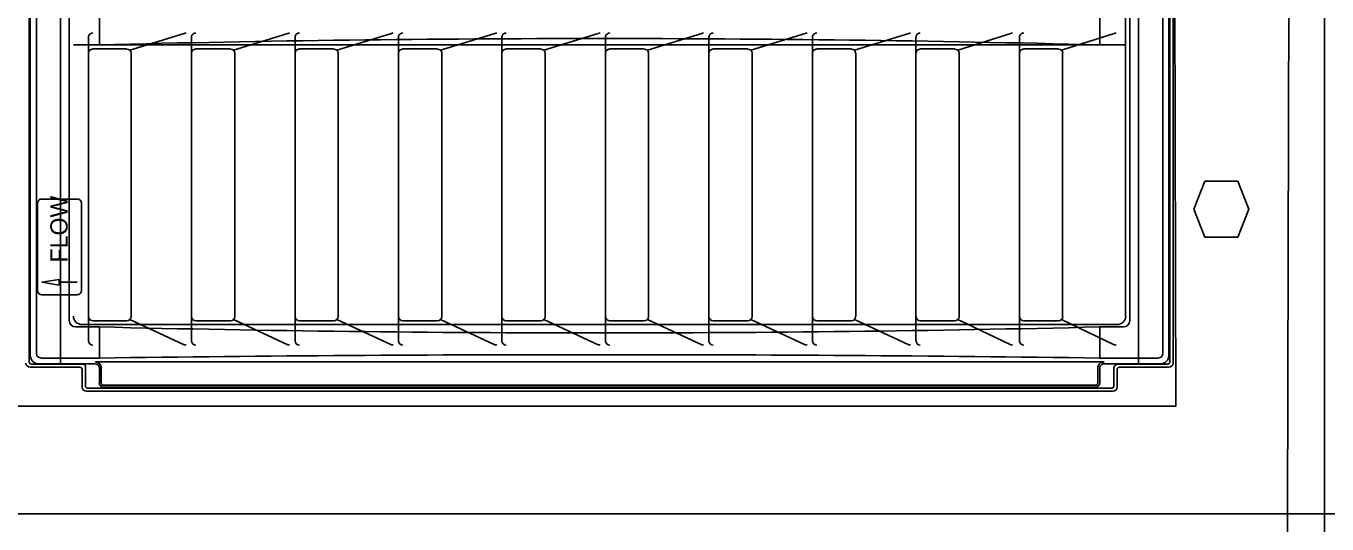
# Model space of a CAD drawing. Extents: x 9.6 to 16.8, y 2.2 to 12.2.
# Drawn here: x 12.408 to 13.549, y 10.385 to 10.822 of the extents above; entities that cross this region are included whole.
import ezdxf

# ---------------------------------------------------------------- set-up
doc = ezdxf.new("R2010")
doc.units = 0
for name, color, linetype in [('DETL-DIMS', 7, 'Continuous'), ('DETL-LINE', 7, 'Continuous'), ('DETL-NOTE', 7, 'Continuous')]:
    doc.layers.add(name, color=color, linetype=linetype)

msp = doc.modelspace()

# ---------------------------------------------------------------- linework, layer by layer
at = {"layer": 'DETL-DIMS'}
for q in [(13.5141, 10.0694), (13.9374, 10.3938)]:
    msp.add_line((13.5141, 10.3938), q, dxfattribs=at)
at = {"layer": 'DETL-LINE'}
for p, q in [((13.5464, 10.3172), (13.5464, 11.6582)), ((13.4162, 10.4884), (13.4137, 11.418)), ((13.5167, 11.4178), (13.5141, 10.3937)), ((12.4104, 10.527), (12.4104, 11.3973)), ((12.4378, 10.5253), (12.4378, 11.3968)), ((13.3835, 10.5253), (13.3835, 11.3968)), ((13.4109, 10.527), (13.4109, 11.3973)), ((13.4137, 10.5261), (13.4137, 11.3982)), ((12.4167, 10.5342), (12.4167, 11.388)), ((13.4046, 10.5342), (13.4046, 11.388)), ((12.4455, 10.5633), (12.4455, 11.3559)), ((13.3721, 10.5672), (13.3721, 11.355)), ((13.3758, 10.5633), (13.3758, 11.3589)), ((12.4719, 10.8052), (12.4719, 10.8383)), ((13.3494, 10.8052), (13.3494, 10.8383)), ((13.3721, 10.8052), (12.4492, 10.8052)), ((13.4318, 10.6611), (13.4417, 10.6858)), ((13.4417, 10.6858), (13.4704, 10.6858)), ((13.4704, 10.6858), (13.4803, 10.6611)), ((13.4417, 10.6365), (13.4318, 10.6611)), ((13.4803, 10.6611), (13.4704, 10.6365)), ((13.4704, 10.6365), (13.4417, 10.6365)), ((12.4719, 10.5578), (12.4512, 10.5578)), ((12.4567, 10.5599), (13.3646, 10.5599)), ((12.4719, 10.5305), (12.4719, 10.5578)), ((13.3494, 10.5578), (13.3701, 10.5578)), ((13.3494, 10.5305), (13.3494, 10.5578)), ((12.4548, 10.5224), (12.4113, 10.5224)), ((12.4577, 10.5252), (12.4123, 10.5252)), ((12.4719, 10.5305), (12.4205, 10.5305)), ((12.4378, 10.5252), (12.4378, 10.5253)), ((12.4596, 10.5059), (12.4596, 10.5233)), ((13.3532, 10.5271), (12.4688, 10.5271)), ((12.4736, 10.5086), (12.4736, 10.5217)), ((13.3476, 10.5086), (13.3476, 10.5217)), ((13.4008, 10.5305), (13.3494, 10.5305)), ((13.3617, 10.5059), (13.3617, 10.5215)), ((13.409, 10.5252), (13.3655, 10.5252)), ((13.41, 10.5224), (13.3665, 10.5224)), ((13.3835, 10.5252), (13.3835, 10.5253)), ((12.4567, 10.505), (12.4567, 10.5206)), ((13.3646, 10.505), (13.3646, 10.5206)), ((13.3608, 10.5013), (12.4605, 10.5013)), ((13.3598, 10.5041), (12.4615, 10.5041)), ((13.3456, 10.5067), (12.4756, 10.5067)), ((11.3604, 10.4884), (13.4162, 10.4884)), ((11.2685, 10.3938), (13.5141, 10.3938))]:
    msp.add_line(p, q, dxfattribs=at)
for centre, major_axis, start_param, end_param in [((12.9106, -5.5583), (16.9691, 0), 1.544936, 1.596657), ((12.4567, 10.5672), (0.00757, 0), 3.141593, 4.712389), ((13.3646, 10.5672), (0.00757, 0), 4.712389, 6.283185), ((12.4512, 10.5633), (0.00567, 0), 3.141593, 4.712389), ((12.9106, 27.6743), (17.7494, 0), 4.687666, 4.737112), ((13.3701, 10.5633), (0.00567, 0), 4.712389, 6.283185), ((12.4205, 10.5342), (0.00378, 0), 3.141593, 4.712389), ((12.9106, -20.1548), (31.8132, 0), 1.557003, 1.584589), ((13.4008, 10.5342), (0.00378, 0), 4.712389, 6.283185), ((12.4113, 10.5261), (0.00378, 0), 3.141593, 4.712389), ((12.4123, 10.527), (0.00189, 0), 3.141593, 4.712389), ((12.4548, 10.5206), (0.00189, 0), 0, 1.570796), ((12.4577, 10.5233), (0.00189, 0), 0, 1.570796), ((12.4681, 10.5217), (0.00556, 0), 0, 1.570796), ((13.3532, 10.5217), (0.00556, 0), 1.570796, 3.141593), ((13.3655, 10.5215), (0.00378, 0), 1.570796, 3.141593), ((13.3665, 10.5206), (0.00189, 0), 1.570796, 3.141593), ((13.409, 10.527), (0.00189, 0), 4.712389, 6.283185), ((13.41, 10.5261), (0.00378, 0), 4.712389, 6.283185), ((12.4605, 10.505), (0.00378, 0), 3.141593, 4.712389), ((12.4615, 10.5059), (0.00189, 0), 3.141593, 4.712389), ((12.4756, 10.5086), (0.002, 0), 3.141593, 4.712389), ((13.3456, 10.5086), (0.002, 0), 4.712389, 6.283185), ((13.3598, 10.5059), (0.00189, 0), 4.712389, 6.283185), ((13.3608, 10.505), (0.00378, 0), 4.712389, 6.283185)]:
    msp.add_ellipse(centre, major_axis=major_axis, ratio=0.964639, start_param=start_param, end_param=end_param, dxfattribs=at)
at = {"layer": 'DETL-NOTE'}
for p, q in [((12.4113, 10.5326), (12.4113, 11.3895)), ((13.41, 10.5326), (13.41, 11.3895)), ((12.4624, 10.812), (12.4624, 10.7844)), ((12.4987, 10.8005), (12.5464, 10.8153)), ((12.5527, 10.812), (12.5527, 10.7844)), ((12.5895, 10.8005), (12.6372, 10.8153)), ((12.6435, 10.812), (12.6435, 10.7844)), ((12.6803, 10.8005), (12.728, 10.8153)), ((12.7343, 10.812), (12.7343, 10.7844)), ((12.771, 10.8005), (12.8187, 10.8153)), ((12.825, 10.812), (12.825, 10.7844)), ((12.8618, 10.8005), (12.9095, 10.8153)), ((12.9158, 10.812), (12.9158, 10.7844)), ((12.9526, 10.8005), (13.0003, 10.8153)), ((13.0066, 10.812), (13.0066, 10.7844)), ((13.0434, 10.8005), (13.0911, 10.8153)), ((13.0974, 10.812), (13.0974, 10.7844)), ((13.1342, 10.8005), (13.1819, 10.8153)), ((13.1882, 10.812), (13.1882, 10.7844)), ((13.225, 10.8005), (13.2713, 10.8153)), ((13.279, 10.812), (13.279, 10.7844)), ((13.3157, 10.8005), (13.362, 10.8153)), ((12.496, 10.8016), (12.4661, 10.8016)), ((12.4998, 10.7979), (12.4998, 10.7844)), ((12.5868, 10.8016), (12.5565, 10.8016)), ((12.5906, 10.7979), (12.5906, 10.7844)), ((12.6776, 10.8016), (12.6473, 10.8016)), ((12.6814, 10.7979), (12.6814, 10.7844)), ((12.7684, 10.8016), (12.738, 10.8016)), ((12.7722, 10.7979), (12.7722, 10.7844)), ((12.8592, 10.8016), (12.8288, 10.8016)), ((12.8629, 10.7979), (12.8629, 10.7844)), ((12.9499, 10.8016), (12.9196, 10.8016)), ((12.9537, 10.7979), (12.9537, 10.7844)), ((13.0407, 10.8016), (13.0104, 10.8016)), ((13.0445, 10.7979), (13.0445, 10.7844)), ((13.1315, 10.8016), (13.1012, 10.8016)), ((13.1353, 10.7979), (13.1353, 10.7844)), ((13.2223, 10.8016), (13.192, 10.8016)), ((13.2261, 10.7979), (13.2261, 10.7844)), ((13.3131, 10.8016), (13.2827, 10.8016)), ((13.3168, 10.7979), (13.3168, 10.7844)), ((12.4624, 10.5455), (12.4624, 10.7844)), ((12.4998, 10.5668), (12.4998, 10.7844)), ((12.5527, 10.5455), (12.5527, 10.7844)), ((12.5906, 10.5668), (12.5906, 10.7844)), ((12.6435, 10.5455), (12.6435, 10.7844)), ((12.6814, 10.5668), (12.6814, 10.7844)), ((12.7343, 10.5455), (12.7343, 10.7844)), ((12.7722, 10.5668), (12.7722, 10.7844)), ((12.825, 10.5455), (12.825, 10.7844)), ((12.8629, 10.5668), (12.8629, 10.7844)), ((12.9158, 10.5455), (12.9158, 10.7844)), ((12.9537, 10.5668), (12.9537, 10.7844)), ((13.0066, 10.5455), (13.0066, 10.7844)), ((13.0445, 10.5668), (13.0445, 10.7844)), ((13.0974, 10.5455), (13.0974, 10.7844)), ((13.1353, 10.5668), (13.1353, 10.7844)), ((13.1882, 10.5455), (13.1882, 10.7844)), ((13.2261, 10.5668), (13.2261, 10.7844)), ((13.279, 10.5455), (13.279, 10.7844)), ((13.3168, 10.5668), (13.3168, 10.7844)), ((12.4215, 10.67), (12.4525, 10.67)), ((12.4177, 10.6664), (12.4177, 10.5897)), ((12.4563, 10.6664), (12.4563, 10.5897)), ((12.4366, 10.597), (12.4523, 10.597)), ((12.4215, 10.586), (12.4525, 10.586)), ((12.496, 10.5632), (12.4661, 10.5632)), ((12.4987, 10.5642), (12.5464, 10.5422)), ((12.5868, 10.5632), (12.5565, 10.5632)), ((12.5895, 10.5642), (12.6372, 10.5422)), ((12.6776, 10.5632), (12.6473, 10.5632)), ((12.6803, 10.5642), (12.728, 10.5422)), ((12.7684, 10.5632), (12.738, 10.5632)), ((12.771, 10.5642), (12.8187, 10.5422)), ((12.8592, 10.5632), (12.8288, 10.5632)), ((12.8618, 10.5642), (12.9095, 10.5422)), ((12.9499, 10.5632), (12.9196, 10.5632)), ((12.9526, 10.5642), (13.0003, 10.5422)), ((13.0407, 10.5632), (13.0104, 10.5632)), ((13.0434, 10.5642), (13.0911, 10.5422)), ((13.1315, 10.5632), (13.1012, 10.5632)), ((13.1342, 10.5642), (13.1819, 10.5422)), ((13.2223, 10.5632), (13.192, 10.5632)), ((13.225, 10.5642), (13.2713, 10.5422)), ((13.3131, 10.5632), (13.2827, 10.5632)), ((13.3157, 10.5642), (13.362, 10.5422)), ((12.4681, 10.5253), (12.4189, 10.5253)), ((12.4719, 10.5086), (12.4719, 10.5217)), ((12.4719, 10.518), (12.4719, 10.5216)), ((13.3494, 10.5086), (13.3494, 10.5217)), ((13.4024, 10.5253), (13.3532, 10.5253)), ((12.4756, 10.505), (13.3456, 10.505))]:
    msp.add_line(p, q, dxfattribs=at)
msp.add_lwpolyline([(12.4366, 10.5945), (12.4366, 10.5994), (12.4215, 10.597)], close=True, dxfattribs=at)
for centre, major_axis, start_param, end_param in [((12.4661, 10.812), (0.00378, 0), 1.570796, 3.141593), ((12.548, 10.812), (0.00378, 0), 1.570796, 2.018093), ((12.5565, 10.812), (0.00378, 0), 1.570796, 3.141593), ((12.6388, 10.812), (0.00378, 0), 1.570796, 2.018093), ((12.6473, 10.812), (0.00378, 0), 1.570796, 3.141593), ((12.7296, 10.812), (0.00378, 0), 1.570796, 2.018093), ((12.738, 10.812), (0.00378, 0), 1.570796, 3.141593), ((12.8204, 10.812), (0.00378, 0), 1.570796, 2.018093), ((12.8288, 10.812), (0.00378, 0), 1.570796, 3.141593), ((12.9112, 10.812), (0.00378, 0), 1.570796, 2.018093), ((12.9196, 10.812), (0.00378, 0), 1.570796, 3.141593), ((13.0019, 10.812), (0.00378, 0), 1.570796, 2.018093), ((13.0104, 10.812), (0.00378, 0), 1.570796, 3.141593), ((13.0927, 10.812), (0.00378, 0), 1.570796, 2.018093), ((13.1012, 10.812), (0.00378, 0), 1.570796, 3.141593), ((13.1835, 10.812), (0.00378, 0), 1.570796, 2.018093), ((13.192, 10.812), (0.00378, 0), 1.570796, 3.141593), ((13.2729, 10.812), (0.00378, 0), 1.570796, 2.018093), ((13.2827, 10.812), (0.00378, 0), 1.570796, 3.141593), ((13.3637, 10.812), (0.00378, 0), 1.570796, 2.018093), ((12.4661, 10.7979), (0.00378, 0), 1.570796, 3.141593), ((12.496, 10.7979), (0.00378, 0), 0, 1.570796), ((12.5565, 10.7979), (0.00378, 0), 1.570796, 3.141593), ((12.5868, 10.7979), (0.00378, 0), 0, 1.570796), ((12.6473, 10.7979), (0.00378, 0), 1.570796, 3.141593), ((12.6776, 10.7979), (0.00378, 0), 0, 1.570796), ((12.738, 10.7979), (0.00378, 0), 1.570796, 3.141593), ((12.7684, 10.7979), (0.00378, 0), 0, 1.570796), ((12.8288, 10.7979), (0.00378, 0), 1.570796, 3.141593), ((12.8592, 10.7979), (0.00378, 0), 0, 1.570796), ((12.9196, 10.7979), (0.00378, 0), 1.570796, 3.141593), ((12.9499, 10.7979), (0.00378, 0), 0, 1.570796), ((13.0104, 10.7979), (0.00378, 0), 1.570796, 3.141593), ((13.0407, 10.7979), (0.00378, 0), 0, 1.570796), ((13.1012, 10.7979), (0.00378, 0), 1.570796, 3.141593), ((13.1315, 10.7979), (0.00378, 0), 0, 1.570796), ((13.192, 10.7979), (0.00378, 0), 1.570796, 3.141593), ((13.2223, 10.7979), (0.00378, 0), 0, 1.570796), ((13.2827, 10.7979), (0.00378, 0), 1.570796, 3.141593), ((13.3131, 10.7979), (0.00378, 0), 0, 1.570796), ((12.4215, 10.6664), (0.00378, 0), 1.570796, 3.141593), ((12.4525, 10.6664), (0.00378, 0), 0, 1.570796), ((12.4215, 10.5897), (0.00378, 0), 3.141593, 4.712389), ((12.4525, 10.5897), (0.00378, 0), 4.712389, 6.283185), ((12.4661, 10.5668), (0.00378, 0), 3.141593, 4.712389), ((12.496, 10.5668), (0.00378, 0), 4.712389, 6.283185), ((12.5565, 10.5668), (0.00378, 0), 3.141593, 4.712389), ((12.5868, 10.5668), (0.00378, 0), 4.712389, 6.283185), ((12.6473, 10.5668), (0.00378, 0), 3.141593, 4.712389), ((12.6776, 10.5668), (0.00378, 0), 4.712389, 6.283185), ((12.738, 10.5668), (0.00378, 0), 3.141593, 4.712389), ((12.7684, 10.5668), (0.00378, 0), 4.712389, 6.283185), ((12.8288, 10.5668), (0.00378, 0), 3.141593, 4.712389), ((12.8592, 10.5668), (0.00378, 0), 4.712389, 6.283185), ((12.9196, 10.5668), (0.00378, 0), 3.141593, 4.712389), ((12.9499, 10.5668), (0.00378, 0), 4.712389, 6.283185), ((13.0104, 10.5668), (0.00378, 0), 3.141593, 4.712389), ((13.0407, 10.5668), (0.00378, 0), 4.712389, 6.283185), ((13.1012, 10.5668), (0.00378, 0), 3.141593, 4.712389), ((13.1315, 10.5668), (0.00378, 0), 4.712389, 6.283185), ((13.192, 10.5668), (0.00378, 0), 3.141593, 4.712389), ((13.2223, 10.5668), (0.00378, 0), 4.712389, 6.283185), ((13.2827, 10.5668), (0.00378, 0), 3.141593, 4.712389), ((13.3131, 10.5668), (0.00378, 0), 4.712389, 6.283185), ((12.4661, 10.5455), (0.00378, 0), 3.141593, 4.712389), ((12.5565, 10.5455), (0.00378, 0), 3.141593, 4.712389), ((12.6473, 10.5455), (0.00378, 0), 3.141593, 4.712389), ((12.738, 10.5455), (0.00378, 0), 3.141593, 4.712389), ((12.8288, 10.5455), (0.00378, 0), 3.141593, 4.712389), ((12.9196, 10.5455), (0.00378, 0), 3.141593, 4.712389), ((13.0104, 10.5455), (0.00378, 0), 3.141593, 4.712389), ((13.1012, 10.5455), (0.00378, 0), 3.141593, 4.712389), ((13.192, 10.5455), (0.00378, 0), 3.141593, 4.712389), ((13.2827, 10.5455), (0.00378, 0), 3.141593, 4.712389), ((12.548, 10.5455), (0.00378, 0), 4.265092, 4.712389), ((12.6388, 10.5455), (0.00378, 0), 4.265092, 4.712389), ((12.7296, 10.5455), (0.00378, 0), 4.265092, 4.712389), ((12.8204, 10.5455), (0.00378, 0), 4.265092, 4.712389), ((12.9112, 10.5455), (0.00378, 0), 4.265092, 4.712389), ((13.0019, 10.5455), (0.00378, 0), 4.265092, 4.712389), ((13.0927, 10.5455), (0.00378, 0), 4.265092, 4.712389), ((13.1835, 10.5455), (0.00378, 0), 4.265092, 4.712389), ((13.2729, 10.5455), (0.00378, 0), 4.265092, 4.712389), ((13.3637, 10.5455), (0.00378, 0), 4.265092, 4.712389), ((12.4189, 10.5326), (0.00757, 0), 3.141593, 4.712389), ((12.4681, 10.5217), (0.00378, 0), 0, 1.570796), ((13.3532, 10.5217), (0.00378, 0), 1.570796, 3.141593), ((13.4024, 10.5326), (0.00757, 0), 4.712389, 6.283185), ((12.4756, 10.5086), (0.00378, 0), 3.141593, 4.712389), ((13.3456, 10.5086), (0.00378, 0), 4.712389, 6.283185)]:
    msp.add_ellipse(centre, major_axis=major_axis, ratio=0.964639, start_param=start_param, end_param=end_param, dxfattribs=at)

# ---------------------------------------------------------------- texts
msp.add_text('FLOW', height=0.01513, rotation=90, dxfattribs=at).set_placement((12.444, 10.6144))

doc.saveas('drawing.dxf')
